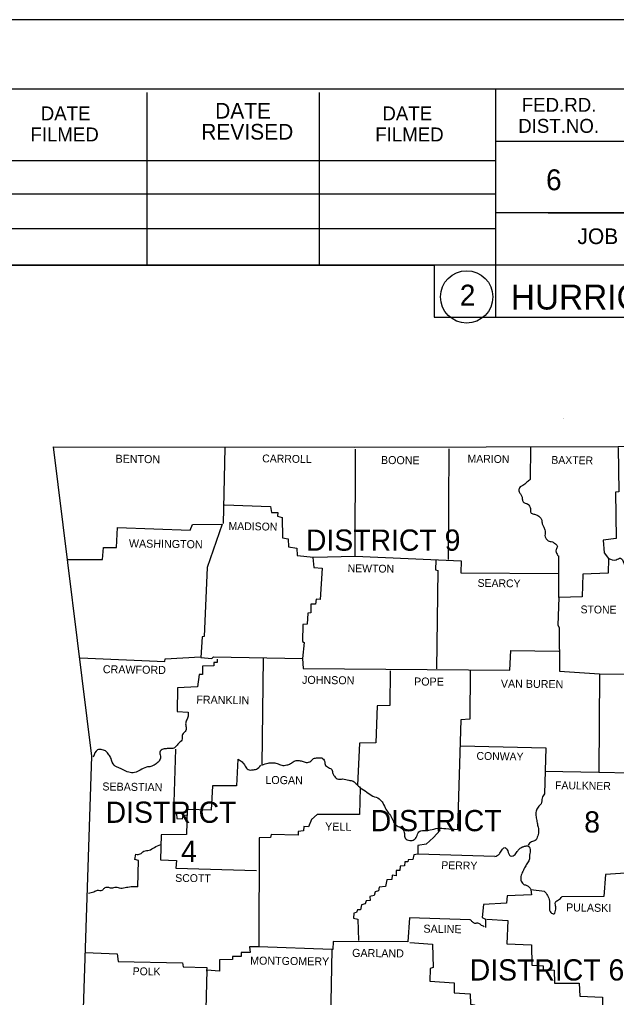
# Model space of a CAD drawing. Extents: x -492261 to -432772, y 1441225 to 1452922.
# Drawn here: x -457494 to -457159, y 1452098 to 1452647 of the extents above; entities that cross this region are included whole.
import ezdxf

# ---------------------------------------------------------------- set-up
doc = ezdxf.new("R2010")
doc.units = 0
for name, color, linetype in [('Default', 7, 'Continuous'), ('R_Border', 7, 'Continuous'), ('R_Border Prem', 7, 'Continuous'), ('R_No Plot', 7, 'Continuous')]:
    doc.layers.add(name, color=color, linetype=linetype)

msp = doc.modelspace()

# ---------------------------------------------------------------- linework, layer by layer
at = {"layer": 'Default'}
msp.add_line((-457318.61, 1452124.91), (-457319.83, 1452059.34), dxfattribs=at)
for points in [[(-457474.92, 1452406.92), (-457306.08, 1452406.81), (-457157.92, 1452407.12), (-456983.14, 1452409.84), (-456902.11, 1452411.72)], [(-457474.92, 1452406.92), (-457453.3, 1452233.39), (-457462.7, 1451950.12)], [(-457378.55, 1452406.29), (-457379.49, 1452364)], [(-457207.1, 1452406.5), (-457207.31, 1452388.64)], [(-457157.92, 1452406.5), (-457157.71, 1452381.65), (-457159.49, 1452381.54), (-457159.18, 1452355.55), (-457166.49, 1452354.5), (-457165.86, 1452347.51), (-457163.35, 1452344.27), (-457163.56, 1452336.02), (-457177.76, 1452335.5), (-457178.28, 1452322.76), (-457191.23, 1452322.34), (-457191.86, 1452306.89), (-457191.13, 1452305.64), (-457190.81, 1452281), (-457168.47, 1452279.54), (-457168.78, 1452224.51), (-457151.03, 1452223.99), (-457151.03, 1452168.03), (-457165.02, 1452166.98), (-457166.07, 1452154.66), (-457189.56, 1452154.56)], [(-457378.75, 1452374.34), (-457353.07, 1452373.5), (-457352.44, 1452370.16), (-457348.89, 1452370.06), (-457349, 1452367.97), (-457346.49, 1452367.34), (-457346.28, 1452355.96), (-457343.05, 1452355.23), (-457342.84, 1452350.74), (-457338.24, 1452350.12), (-457338.03, 1452345.94), (-457328.95, 1452345), (-457305.56, 1452345.52), (-457305.35, 1452405.56)], [(-457253.04, 1452405.77), (-457253.36, 1452343.75)], [(-457466.67, 1452343.75), (-457447.14, 1452343.64), (-457446.62, 1452350.53), (-457439.42, 1452350.53), (-457438.79, 1452361.71), (-457398.07, 1452360.24), (-457396.82, 1452363.38), (-457380.01, 1452363.48), (-457388.47, 1452339.26), (-457390.14, 1452300.52), (-457391.39, 1452300.42), (-457392.02, 1452288.72), (-457385.85, 1452288.2), (-457384.92, 1452289.14), (-457335.11, 1452288.2), (-457334.59, 1452282.67)], [(-457191.23, 1452322.34), (-457191.34, 1452345.84)], [(-457329.16, 1452344.79), (-457328.74, 1452339.15), (-457323.94, 1452338.84), (-457325.19, 1452321.3), (-457327.38, 1452321.4), (-457327.8, 1452318.58), (-457330.31, 1452318.58), (-457330.41, 1452313.78), (-457331.98, 1452313.68), (-457332.5, 1452307.52), (-457334.8, 1452307.2), (-457335.11, 1452297.81), (-457334.07, 1452297.08), (-457335.11, 1452288.2)], [(-457305.56, 1452345.52), (-457246.05, 1452343.02), (-457246.15, 1452336.23), (-457191.54, 1452335.81)], [(-457260.35, 1452343.33), (-457260.46, 1452337.9), (-457259.1, 1452337.59), (-457259.93, 1452282.46)], [(-457334.59, 1452282.67), (-457218.69, 1452281.73), (-457218.17, 1452292.69), (-457191.23, 1452292.38)], [(-457459.78, 1452288.62), (-457412.27, 1452286.43), (-457412.06, 1452288.1), (-457392.22, 1452289.04)], [(-457382.83, 1452287.78), (-457382.83, 1452285.9), (-457384.81, 1452285.9), (-457384.71, 1452284.03), (-457391.08, 1452283.92), (-457391.18, 1452279.22), (-457392.95, 1452279.22), (-457393.89, 1452272.23), (-457405.17, 1452271.71), (-457405.28, 1452258.45), (-457399.22, 1452258.03)], [(-457357.04, 1452288.62), (-457357.77, 1452228.38)], [(-457285.9, 1452281.34), (-457286.01, 1452261.82), (-457293.21, 1452261.72), (-457293.84, 1452240.94), (-457303.03, 1452240.62), (-457304.17, 1452217.2)], [(-457240.93, 1452281.31), (-457241.14, 1452254.16), (-457246.15, 1452253.75), (-457248.14, 1452192.35)], [(-457168.47, 1452279.54), (-457114.8, 1452279.22), (-457110.21, 1452281.42), (-457110.52, 1452240.59), (-457113.65, 1452239.23), (-457116.47, 1452236.83), (-457117.41, 1452235.89), (-457117.52, 1452224.2), (-457151.66, 1452224.2)], [(-457406.32, 1452237.35), (-457407.36, 1452201.44), (-457405.8, 1452201.02), (-457405.48, 1452198.51), (-457402.35, 1452198.31), (-457402.04, 1452200.08), (-457399.53, 1452200.5)], [(-457246.36, 1452239.23), (-457198.64, 1452238.09), (-457199.27, 1452212.3)], [(-457371.24, 1452231.72), (-457371.97, 1452216.79), (-457385.54, 1452216.68), (-457386.27, 1452203.11), (-457399.74, 1452203.42), (-457400.16, 1452189.43), (-457414.25, 1452189.33), (-457414.67, 1452175.34), (-457405.8, 1452174.81), (-457406.11, 1452170.53), (-457360.8, 1452169.28)], [(-457199.17, 1452224.93), (-457168.78, 1452224.51)], [(-457302.64, 1452215.74), (-457303.06, 1452200.71), (-457326.86, 1452200.6), (-457329.99, 1452197.89), (-457331.77, 1452193.71), (-457334.38, 1452193.92), (-457334.48, 1452191.52), (-457337.51, 1452191.21), (-457337.41, 1452189.01), (-457352.55, 1452189.43), (-457353.07, 1452187.76), (-457359.33, 1452187.55), (-457359.54, 1452126.47), (-457364.76, 1452126.37), (-457364.35, 1452123.24), (-457369.36, 1452123.34), (-457369.46, 1452121.04), (-457374.37, 1452121.04), (-457374.27, 1452119.37), (-457381.57, 1452119.16), (-457381.68, 1452112.79), (-457388.78, 1452113.42), (-457389.93, 1452062.05)], [(-457257.85, 1452191.94), (-457261.6, 1452187.86), (-457265.68, 1452184), (-457270.38, 1452183.27), (-457270.38, 1452178.36), (-457272.67, 1452178.05), (-457273.09, 1452175.54), (-457275.7, 1452175.34), (-457275.91, 1452174.19), (-457277.68, 1452174.08), (-457277.79, 1452171.89), (-457280.29, 1452171.79), (-457280.5, 1452169.28), (-457282.59, 1452169.28), (-457282.49, 1452166.36), (-457284.78, 1452166.57), (-457284.89, 1452164.27), (-457287.71, 1452164.06), (-457288.54, 1452160.3), (-457292.09, 1452159.99), (-457292.41, 1452157.9), (-457294.29, 1452157.38), (-457294.81, 1452155.18), (-457297.21, 1452154.66), (-457297, 1452152.47), (-457299.4, 1452152.26), (-457299.82, 1452150.59), (-457302.01, 1452149.96), (-457302.53, 1452147.14), (-457304.2, 1452147.25), (-457304.73, 1452145.79), (-457306.29, 1452145.27), (-457306.4, 1452142.45), (-457304, 1452142.03), (-457303.58, 1452129.92)], [(-457427.31, 1452160.2), (-457426.99, 1452174.92), (-457429.08, 1452175.54), (-457428.45, 1452178.36)], [(-457227.25, 1452177.11), (-457270.27, 1452178.47)], [(-457199.38, 1452157.59), (-457206.89, 1452158.42), (-457206.58, 1452155.6), (-457220.26, 1452155.08), (-457220.68, 1452151.01), (-457233.52, 1452150.28), (-457234.25, 1452142.97), (-457232.37, 1452142.03), (-457232.37, 1452137.23)], [(-457240.93, 1452141.61), (-457275.07, 1452142.66), (-457276.01, 1452129.19), (-457317.78, 1452129.4), (-457317.95, 1452124.88)], [(-457231.64, 1452141.92), (-457219.94, 1452141.19), (-457220.36, 1452128.14), (-457206.68, 1452127.62), (-457206.48, 1452116.24), (-457200, 1452115.72), (-457200, 1452113.73), (-457193.95, 1452113.32), (-457193.74, 1452106.01), (-457179.95, 1452106.01), (-457179.54, 1452098.8), (-457166.8, 1452098.18), (-457166.9, 1452084.6)], [(-457318.61, 1452124.91), (-457359.54, 1452126.47)], [(-457274.76, 1452128.98), (-457262.13, 1452128.04), (-457261.71, 1452114.88), (-457263.48, 1452114.26), (-457263.69, 1452107.26), (-457250.01, 1452106.32), (-457250.01, 1452100.58), (-457240.93, 1452100.06), (-457240.83, 1452094.31), (-457238.63, 1452094), (-457238.74, 1452086.27)], [(-457456.96, 1452123.24), (-457438.9, 1452122.61), (-457438.48, 1452118.22), (-457402.35, 1452117.49), (-457401.93, 1452115.2), (-457388.78, 1452114.78), (-457388.88, 1452112.79)], [(-457317.95, 1452124.88), (-457318.61, 1452124.91)]]:
    msp.add_lwpolyline(points, dxfattribs=at)
for points in [[(-457207.31, 1452388.64), (-457209.19, 1452387.08), (-457210.86, 1452385.62), (-457213.37, 1452383.84), (-457213.68, 1452382.17), (-457212.84, 1452380.5), (-457212.01, 1452379.14), (-457211.7, 1452377.26), (-457210.96, 1452375.7), (-457209.19, 1452375.07), (-457207.73, 1452373.71), (-457207.21, 1452371.83), (-457207, 1452370.06), (-457205.33, 1452369.22), (-457203.45, 1452368.6), (-457201.67, 1452367.34), (-457200.84, 1452365.78), (-457200.63, 1452363.79), (-457199.9, 1452362.23), (-457199.06, 1452360.35), (-457198.85, 1452358.78), (-457199.06, 1452357.22), (-457198.64, 1452355.75), (-457197.29, 1452354.29), (-457194.89, 1452353.56), (-457193.21, 1452352.52), (-457192.07, 1452351.06), (-457192.8, 1452349.28), (-457192.69, 1452347.72), (-457191.75, 1452345.84)], [(-457163.35, 1452344.27), (-457159.18, 1452343.54), (-457156.67, 1452344.48), (-457154.9, 1452341.76), (-457153.96, 1452339.68), (-457152.39, 1452336.65), (-457149.88, 1452335.71), (-457148, 1452334.04), (-457148, 1452332.26), (-457149.68, 1452330.59), (-457150.93, 1452328.92), (-457150.51, 1452326.94), (-457150.09, 1452324.22), (-457150.09, 1452321.61), (-457150.72, 1452319.21), (-457151.24, 1452317.02), (-457150.72, 1452315.14), (-457148.74, 1452315.45), (-457146.65, 1452317.02), (-457144.45, 1452317.02), (-457142.37, 1452315.87), (-457140.17, 1452313.89), (-457137.98, 1452314.3), (-457136.21, 1452314.83), (-457133.7, 1452315.56), (-457131.93, 1452314.62), (-457130.36, 1452313.36), (-457128.48, 1452311.38), (-457126.7, 1452310.13), (-457124.41, 1452308.98), (-457121.59, 1452308.25), (-457118.98, 1452306.47), (-457118.56, 1452303.45), (-457118.66, 1452300.84), (-457118.87, 1452297.6), (-457119.08, 1452294.05), (-457118.77, 1452290.6), (-457117.62, 1452288.31), (-457116.16, 1452285.59), (-457115.74, 1452283.09), (-457115.85, 1452279.12)], [(-457399.22, 1452258.03), (-457399.22, 1452255.83), (-457400.05, 1452253.54), (-457400.58, 1452251.55), (-457400.26, 1452248.94), (-457401.2, 1452246.86), (-457402.56, 1452245.19), (-457402.56, 1452243.1), (-457404.13, 1452240.9), (-457405.8, 1452239.23), (-457407.26, 1452237.88), (-457409.87, 1452237.67), (-457412.06, 1452237.56), (-457414.25, 1452236.83), (-457415.09, 1452235.27), (-457414.67, 1452232.86), (-457415.51, 1452230.57), (-457417.7, 1452228.79), (-457420.1, 1452227.64), (-457422.61, 1452227.23), (-457426.05, 1452225.56), (-457429.19, 1452224.2), (-457432.53, 1452224.41), (-457435.66, 1452225.77), (-457438.48, 1452227.02), (-457440.67, 1452228.27), (-457442.45, 1452232.13), (-457443.59, 1452234.22), (-457445.58, 1452236.31), (-457447.98, 1452237.15), (-457449.96, 1452236.94), (-457452.37, 1452232.86)], [(-457371.24, 1452231.72), (-457368.94, 1452230.25), (-457367.17, 1452227.85), (-457365.6, 1452225.87), (-457362.99, 1452225.77), (-457360.9, 1452226.18), (-457358.5, 1452228.27)], [(-457357.77, 1452228.38), (-457354.32, 1452229.52), (-457351.82, 1452229.73), (-457349.31, 1452229.32), (-457346.7, 1452228.27), (-457343.88, 1452228.48), (-457341.79, 1452229.21), (-457339.7, 1452230.57), (-457337.41, 1452230.99), (-457335.22, 1452230.57), (-457332.92, 1452229.94), (-457330.41, 1452230.67), (-457328.95, 1452232.03), (-457326.44, 1452232.45), (-457324.25, 1452232.45), (-457322.69, 1452230.67), (-457322.37, 1452228.79), (-457320.39, 1452227.02), (-457318.61, 1452225.87), (-457318.09, 1452223.68), (-457317.15, 1452222.11), (-457316.21, 1452221.07), (-457314.85, 1452220.44), (-457312.56, 1452220.65), (-457309.01, 1452219.92), (-457306.71, 1452219.4), (-457304.62, 1452217.62), (-457302.64, 1452215.74)], [(-457302.64, 1452215.74), (-457298.98, 1452213.24), (-457295.54, 1452211.04), (-457291.99, 1452209.48), (-457290, 1452207.18), (-457288.23, 1452203.63), (-457286.77, 1452201.44), (-457284.89, 1452198.72), (-457283.53, 1452195.7), (-457281.34, 1452194.02), (-457279.04, 1452192.56), (-457277.89, 1452189.95), (-457277.37, 1452187.34), (-457274.86, 1452186.09), (-457272.46, 1452186.61), (-457271.11, 1452188.18), (-457269.85, 1452190.89), (-457267.03, 1452191.73), (-457263.38, 1452192.04), (-457259.2, 1452192.98), (-457254.61, 1452192.77), (-457248.14, 1452192.35)], [(-457199.27, 1452212.3), (-457200.63, 1452209.89), (-457201.25, 1452206.76), (-457202.93, 1452204.78), (-457203.97, 1452202.48), (-457204.07, 1452199.45), (-457203.55, 1452196.74), (-457203.03, 1452194.13), (-457202.61, 1452191.73), (-457203.13, 1452188.7), (-457204.49, 1452186.09), (-457206.58, 1452185.36), (-457208.56, 1452183.58)], [(-457428.45, 1452178.36), (-457426.16, 1452178.57), (-457423.97, 1452180.03), (-457421.04, 1452180.66), (-457418.12, 1452182.23), (-457414.46, 1452183.9)], [(-457227.25, 1452177.11), (-457224.64, 1452178.57), (-457223.29, 1452180.76), (-457221.61, 1452182.12), (-457219.94, 1452180.24), (-457218.48, 1452177.53), (-457216.92, 1452177.53), (-457214.93, 1452179.41), (-457213.68, 1452181.08), (-457212.11, 1452182.33), (-457210.44, 1452182.85), (-457208.67, 1452183.06), (-457207.31, 1452181.08), (-457207.73, 1452177.95), (-457207.73, 1452175.86), (-457208.88, 1452173.66), (-457210.13, 1452171.37), (-457211.49, 1452168.76), (-457212.53, 1452165.94), (-457212.32, 1452163.22), (-457210.86, 1452161.45), (-457209.19, 1452160.93), (-457206.89, 1452158.63)], [(-457427.31, 1452160.2), (-457430.33, 1452160.09), (-457433.78, 1452159.67), (-457436.91, 1452159.26), (-457439.73, 1452159.78), (-457442.34, 1452159.36), (-457444.12, 1452159.78), (-457446.31, 1452159.26), (-457447.56, 1452158), (-457450.17, 1452158), (-457452.05, 1452157.17), (-457455.08, 1452156.44)], [(-457199.38, 1452157.59), (-457197.6, 1452155.29), (-457196.56, 1452152.16), (-457196.56, 1452148.61), (-457195.72, 1452145.68), (-457194.05, 1452145.06), (-457193.01, 1452147.56), (-457193.21, 1452150.07), (-457193.21, 1452151.53), (-457191.44, 1452152.78), (-457189.56, 1452154.56)], [(-457233.1, 1452137.75), (-457235.08, 1452138.79), (-457236.65, 1452139.73), (-457238.32, 1452139.63), (-457239.68, 1452140.46), (-457240.93, 1452141.61)]]:
    msp.add_spline(points, degree=3, dxfattribs=at)
at = {"layer": 'R_Border'}
for p, q in [((-459957.64, 1452607.65), (-456795.84, 1452607.65)), ((-457422.24, 1452508.85), (-457422.24, 1452605.65)), ((-457325.44, 1452508.85), (-457325.44, 1452605.65)), ((-457226.84, 1452607.65), (-457226.84, 1452479.65)), ((-456795.84, 1452578.25), (-457226.84, 1452578.25)), ((-457618.44, 1452567.45), (-457226.84, 1452567.45)), ((-457618.44, 1452548.85), (-457226.84, 1452548.85)), ((-456795.84, 1452538.25), (-457226.84, 1452538.25)), ((-457197.24, 1452538.25), (-456795.84, 1452538.25)), ((-457618.44, 1452529.45), (-457226.84, 1452529.45)), ((-456795.84, 1452508.85), (-457618.44, 1452508.85)), ((-457226.84, 1452479.65), (-456795.84, 1452479.65))]:
    msp.add_line(p, q, dxfattribs=at)
msp.add_circle((-457242.97, 1452491.01), 14.67, dxfattribs=at)
at = {"layer": 'R_No Plot'}
msp.add_line((-460081.65, 1452646.6), (-456748.31, 1452646.6), dxfattribs=at)
for points in [[(-460081.71, 1452646.6), (-456748.31, 1452646.6), (-456748.31, 1450513.22), (-460081.71, 1450513.22)], [(-457618.44, 1452607.65), (-457618.44, 1452508.85), (-457261.12, 1452508.85), (-457261.12, 1452479.65), (-457029.12, 1452479.65), (-457029.12, 1452236.32), (-456795.84, 1452236.32), (-456795.84, 1450553.05), (-459957.64, 1450553.05), (-459957.64, 1452607.65)]]:
    msp.add_lwpolyline(points, close=True, dxfattribs=at)

# ---------------------------------------------------------------- texts
at = {"layer": 'Default'}
for s, height, rotation, p in [('BENTON', 4.49, 359.2527, (-457439.94, 1452398.04)), ('CARROLL', 4.386, 359.1481, (-457357.66, 1452398.25)), ('BOONE', 4.49, 359.4001, (-457291.05, 1452397.31)), ('MARION', 4.386, 359.1854, (-457242.5, 1452398.14)), ('BAXTER', 4.386, 359.256, (-457195.51, 1452397.41)), ('MADISON', 4.386, 359.0906, (-457376.56, 1452360.35)), ('WASHINGTON', 4.489, 359.232, (-457432.42, 1452350.53)), ('NEWTON', 4.386, 359.2717, (-457309.74, 1452336.65)), ('SEARCY', 4.384, 359.2527, (-457236.86, 1452328.4)), ('STONE', 4.384, 359.4001, (-457179.12, 1452313.57)), ('CRAWFORD', 4.489, 359.2771, (-457447.04, 1452279.95)), ('JOHNSON', 4.49, 359.3514, (-457335.32, 1452274)), ('POPE', 4.49, 359.6155, (-457272.46, 1452273.06)), ('VAN BUREN', 4.49, 359.3508, (-457223.81, 1452271.91)), ('FRANKLIN', 4.49, 359.1816, (-457394.63, 1452262.93)), ('CONWAY', 4.384, 359.0372, (-457237.49, 1452231.4)), ('LOGAN', 4.49, 359.3969, (-457355.89, 1452217.83)), ('SEBASTIAN', 4.489, 359.2816, (-457447.35, 1452214.18)), ('FAULKNER', 4.386, 359.2486, (-457193.42, 1452214.91)), ('YELL', 4.49, 359.1987, (-457322.37, 1452191.73)), ('PERRY', 4.386, 359.0858, (-457257.22, 1452170.11)), ('SCOTT', 4.386, 359.4063, (-457406.42, 1452162.91)), ('PULASKI', 4.49, 359.0531, (-457187.26, 1452146.41)), ('SALINE', 4.49, 359.1492, (-457267.24, 1452134.41)), ('MONTGOMERY', 4.49, 359.2944, (-457364.45, 1452116.55)), ('GARLAND', 4.49, 359.3658, (-457307.23, 1452120.83)), ('POLK', 4.384, 359.2152, (-457430.33, 1452110.6))]:
    msp.add_text(s, height=height, rotation=rotation, dxfattribs=at).set_placement(p)
for s, height, p in [('DISTRICT 9', 11.903, (-457333.13, 1452348.65)), ('DISTRICT', 11.903, (-457445.47, 1452196.01)), ('DISTRICT', 11.903, (-457296.79, 1452191.31)), ('8', 11.9, (-457177.03, 1452190.58)), ('4', 11.9, (-457403.19, 1452174.08)), ('DISTRICT 6', 11.903, (-457241.24, 1452107.57))]:
    msp.add_text(s, height=height, dxfattribs=at).set_placement(p)
at = {"layer": 'R_Border'}
for s, height, p in [('DATE', 8.792, (-457384.04, 1452591.05)), ('FED.RD.', 7.819, (-457212.04, 1452594.85)), ('DATE', 7.819, (-457481.84, 1452590.05)), ('DATE', 7.819, (-457290.24, 1452590.05)), ('REVISED', 8.792, (-457391.84, 1452579.25)), ('DIST.NO.', 7.819, (-457214.04, 1452583.05)), ('FILMED', 7.819, (-457487.64, 1452578.25)), ('FILMED', 7.819, (-457294.24, 1452578.25)), ('6', 11.72, (-457198.44, 1452550.85)), ('JOB NO.', 8.792, (-457180.84, 1452520.65)), ('2', 11.72, (-457246.8, 1452486.14)), ('HURRICANE CREEK STR.  & APPRS. (S)', 14, (-457218.2, 1452483.95))]:
    msp.add_text(s, height=height, dxfattribs=at).set_placement(p)
at = {"layer": 'R_Border Prem'}
msp.add_text('DWB', height=0.1, dxfattribs=at).set_placement((-457188.86, 1452422.77))

doc.saveas('drawing.dxf')
